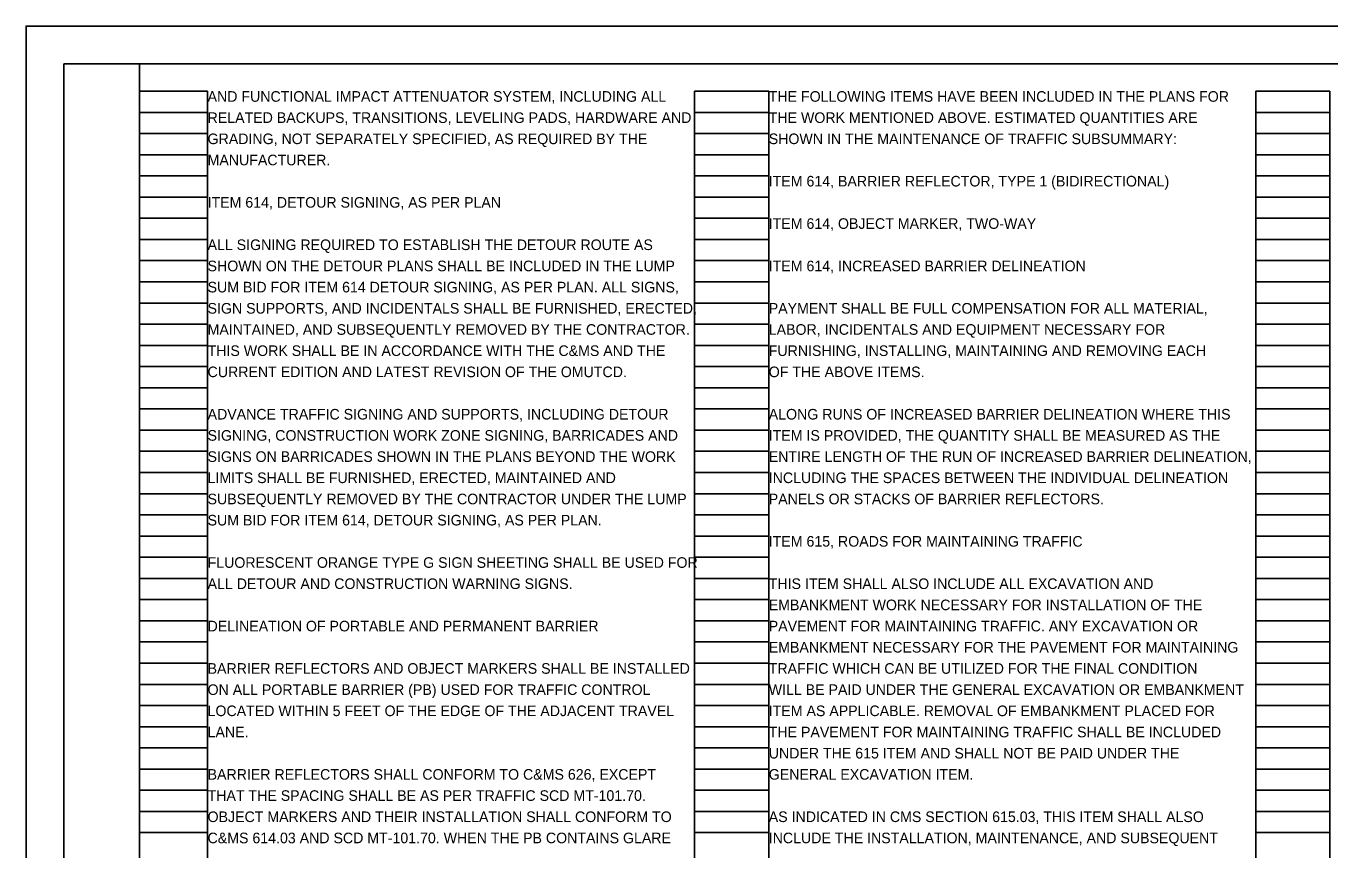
# Model space of a CAD drawing. Extents: x -50 to 112, y -27 to 22.
# Drawn here: x 78 to 95.24, y 11.11 to 22 of the extents above; entities that cross this region are included whole.
import ezdxf

# ---------------------------------------------------------------- set-up
doc = ezdxf.new("R2010")
doc.units = 0
for name, color, linetype in [('SC_Scratch1', 7, 'Continuous'), ('SH_Border', 7, 'Continuous'), ('SH_Cut_Line', 7, 'Continuous'), ('SH_Text', 7, 'Continuous')]:
    doc.layers.add(name, color=color, linetype=linetype)

msp = doc.modelspace()

# ---------------------------------------------------------------- linework, layer by layer
at = {"layer": 'SC_Scratch1'}
for p, q in [((79.5, 0.98), (79.5, 21.14)), ((79.5, 21.14), (80.4, 21.14)), ((80.4, 0.98), (80.4, 21.14)), ((86.84, 0.98), (86.84, 21.14)), ((86.84, 21.14), (87.82, 21.14)), ((87.82, 0.98), (87.82, 21.14)), ((94.26, 0.98), (94.26, 21.14)), ((94.26, 21.14), (95.24, 21.14)), ((95.24, 0.98), (95.24, 21.14)), ((79.5, 20.86), (80.4, 20.86)), ((86.84, 20.86), (87.82, 20.86)), ((94.26, 20.86), (95.24, 20.86)), ((79.5, 20.58), (80.4, 20.58)), ((86.84, 20.58), (87.82, 20.58)), ((94.26, 20.58), (95.24, 20.58)), ((79.5, 20.3), (80.4, 20.3)), ((86.84, 20.3), (87.82, 20.3)), ((94.26, 20.3), (95.24, 20.3)), ((79.5, 20.02), (80.4, 20.02)), ((86.84, 20.02), (87.82, 20.02)), ((94.26, 20.02), (95.24, 20.02)), ((79.5, 19.74), (80.4, 19.74)), ((86.84, 19.74), (87.82, 19.74)), ((94.26, 19.74), (95.24, 19.74)), ((79.5, 19.46), (80.4, 19.46)), ((86.84, 19.46), (87.82, 19.46)), ((94.26, 19.46), (95.24, 19.46)), ((79.5, 19.18), (80.4, 19.18)), ((86.84, 19.18), (87.82, 19.18)), ((94.26, 19.18), (95.24, 19.18)), ((79.5, 18.9), (80.4, 18.9)), ((86.84, 18.9), (87.82, 18.9)), ((94.26, 18.9), (95.24, 18.9)), ((79.5, 18.62), (80.4, 18.62)), ((86.84, 18.62), (87.82, 18.62)), ((94.26, 18.62), (95.24, 18.62)), ((79.5, 18.34), (80.4, 18.34)), ((86.84, 18.34), (87.82, 18.34)), ((94.26, 18.34), (95.24, 18.34)), ((79.5, 18.06), (80.4, 18.06)), ((86.84, 18.06), (87.82, 18.06)), ((94.26, 18.06), (95.24, 18.06)), ((79.5, 17.78), (80.4, 17.78)), ((86.84, 17.78), (87.82, 17.78)), ((94.26, 17.78), (95.24, 17.78)), ((79.5, 17.5), (80.4, 17.5)), ((86.84, 17.5), (87.82, 17.5)), ((94.26, 17.5), (95.24, 17.5)), ((79.5, 17.22), (80.4, 17.22)), ((86.84, 17.22), (87.82, 17.22)), ((94.26, 17.22), (95.24, 17.22)), ((79.5, 16.94), (80.4, 16.94)), ((86.84, 16.94), (87.82, 16.94)), ((94.26, 16.94), (95.24, 16.94)), ((79.5, 16.66), (80.4, 16.66)), ((86.84, 16.66), (87.82, 16.66)), ((94.26, 16.66), (95.24, 16.66)), ((79.5, 16.38), (80.4, 16.38)), ((86.84, 16.38), (87.82, 16.38)), ((94.26, 16.38), (95.24, 16.38)), ((79.5, 16.1), (80.4, 16.1)), ((86.84, 16.1), (87.82, 16.1)), ((94.26, 16.1), (95.24, 16.1)), ((79.5, 15.82), (80.4, 15.82)), ((86.84, 15.82), (87.82, 15.82)), ((94.26, 15.82), (95.24, 15.82)), ((79.5, 15.54), (80.4, 15.54)), ((86.84, 15.54), (87.82, 15.54)), ((94.26, 15.54), (95.24, 15.54)), ((79.5, 15.26), (80.4, 15.26)), ((86.84, 15.26), (87.82, 15.26)), ((94.26, 15.26), (95.24, 15.26)), ((79.5, 14.98), (80.4, 14.98)), ((86.84, 14.98), (87.82, 14.98)), ((94.26, 14.98), (95.24, 14.98)), ((79.5, 14.7), (80.4, 14.7)), ((86.84, 14.7), (87.82, 14.7)), ((94.26, 14.7), (95.24, 14.7)), ((79.5, 14.42), (80.4, 14.42)), ((86.84, 14.42), (87.82, 14.42)), ((94.26, 14.42), (95.24, 14.42)), ((79.5, 14.14), (80.4, 14.14)), ((86.84, 14.14), (87.82, 14.14)), ((94.26, 14.14), (95.24, 14.14)), ((79.5, 13.86), (80.4, 13.86)), ((86.84, 13.86), (87.82, 13.86)), ((94.26, 13.86), (95.24, 13.86)), ((79.5, 13.58), (80.4, 13.58)), ((86.84, 13.58), (87.82, 13.58)), ((94.26, 13.58), (95.24, 13.58)), ((79.5, 13.3), (80.4, 13.3)), ((86.84, 13.3), (87.82, 13.3)), ((94.26, 13.3), (95.24, 13.3)), ((79.5, 13.02), (80.4, 13.02)), ((86.84, 13.02), (87.82, 13.02)), ((94.26, 13.02), (95.24, 13.02)), ((79.5, 12.74), (80.4, 12.74)), ((86.84, 12.74), (87.82, 12.74)), ((94.26, 12.74), (95.24, 12.74)), ((79.5, 12.46), (80.4, 12.46)), ((86.84, 12.46), (87.82, 12.46)), ((94.26, 12.46), (95.24, 12.46)), ((79.5, 12.18), (80.4, 12.18)), ((86.84, 12.18), (87.82, 12.18)), ((94.26, 12.18), (95.24, 12.18)), ((79.5, 11.9), (80.4, 11.9)), ((86.84, 11.9), (87.82, 11.9)), ((94.26, 11.9), (95.24, 11.9)), ((79.5, 11.62), (80.4, 11.62)), ((86.84, 11.62), (87.82, 11.62)), ((94.26, 11.62), (95.24, 11.62)), ((79.5, 11.34), (80.4, 11.34)), ((86.84, 11.34), (87.82, 11.34)), ((94.26, 11.34), (95.24, 11.34))]:
    msp.add_line(p, q, dxfattribs=at)
at = {"layer": 'SH_Border'}
for points in [[(78.5, 21.5), (79.5, 21.5), (79.5, 0.5), (78.5, 0.5)], [(79.5, 21.5), (111.5, 21.5), (111.5, 0.5), (79.5, 0.5)]]:
    msp.add_lwpolyline(points, close=True, dxfattribs=at)
at = {"layer": 'SH_Cut_Line'}
msp.add_lwpolyline([(78, 0), (112, 0), (112, 22), (78, 22)], close=True, dxfattribs=at)

# ---------------------------------------------------------------- texts
at = {"layer": 'SH_Text'}
for s, p in [('AND FUNCTIONAL IMPACT ATTENUATOR SYSTEM, INCLUDING ALL ', (80.4, 21)), ('THE FOLLOWING ITEMS HAVE BEEN INCLUDED IN THE PLANS FOR', (87.82, 21)), ('RELATED BACKUPS, TRANSITIONS, LEVELING PADS, HARDWARE AND ', (80.4, 20.72)), ('THE WORK MENTIONED ABOVE. ESTIMATED QUANTITIES ARE ', (87.82, 20.72)), ('GRADING, NOT SEPARATELY SPECIFIED, AS REQUIRED BY THE ', (80.4, 20.44)), ('SHOWN IN THE MAINTENANCE OF TRAFFIC SUBSUMMARY:', (87.82, 20.44)), ('MANUFACTURER.', (80.4, 20.16)), ('ITEM 614, BARRIER REFLECTOR, TYPE 1 (BIDIRECTIONAL)', (87.82, 19.88)), ('ITEM 614, DETOUR SIGNING, AS PER PLAN', (80.4, 19.6)), ('ITEM 614, OBJECT MARKER, TWO-WAY', (87.82, 19.32)), ('ALL SIGNING REQUIRED TO ESTABLISH THE DETOUR ROUTE AS ', (80.4, 19.04)), ('SHOWN ON THE DETOUR PLANS SHALL BE INCLUDED IN THE LUMP ', (80.4, 18.76)), ('ITEM 614, INCREASED BARRIER DELINEATION', (87.82, 18.76)), ('SUM BID FOR ITEM 614 DETOUR SIGNING, AS PER PLAN. ALL SIGNS, ', (80.4, 18.48)), ('SIGN SUPPORTS, AND INCIDENTALS SHALL BE FURNISHED, ERECTED, ', (80.4, 18.2)), ('PAYMENT SHALL BE FULL COMPENSATION FOR ALL MATERIAL,', (87.82, 18.2)), ('MAINTAINED, AND SUBSEQUENTLY REMOVED BY THE CONTRACTOR. ', (80.4, 17.92)), ('LABOR, INCIDENTALS AND EQUIPMENT NECESSARY FOR ', (87.82, 17.92)), ('THIS WORK SHALL BE IN ACCORDANCE WITH THE C&MS AND THE ', (80.4, 17.64)), ('FURNISHING, INSTALLING, MAINTAINING AND REMOVING EACH', (87.82, 17.64)), ('CURRENT EDITION AND LATEST REVISION OF THE OMUTCD. ', (80.4, 17.36)), ('OF THE ABOVE ITEMS.', (87.82, 17.36)), ('ADVANCE TRAFFIC SIGNING AND SUPPORTS, INCLUDING DETOUR ', (80.4, 16.8)), ('ALONG RUNS OF INCREASED BARRIER DELINEATION WHERE THIS ', (87.82, 16.8)), ('SIGNING, CONSTRUCTION WORK ZONE SIGNING, BARRICADES AND ', (80.4, 16.52)), ('ITEM IS PROVIDED, THE QUANTITY SHALL BE MEASURED AS THE ', (87.82, 16.52)), ('SIGNS ON BARRICADES SHOWN IN THE PLANS BEYOND THE WORK ', (80.4, 16.24)), ('ENTIRE LENGTH OF THE RUN OF INCREASED BARRIER DELINEATION, ', (87.82, 16.24)), ('LIMITS SHALL BE FURNISHED, ERECTED, MAINTAINED AND ', (80.4, 15.96)), ('INCLUDING THE SPACES BETWEEN THE INDIVIDUAL DELINEATION ', (87.82, 15.96)), ('SUBSEQUENTLY REMOVED BY THE CONTRACTOR UNDER THE LUMP ', (80.4, 15.68)), ('PANELS OR STACKS OF BARRIER REFLECTORS.', (87.82, 15.68)), ('SUM BID FOR ITEM 614, DETOUR SIGNING, AS PER PLAN.', (80.4, 15.4)), ('ITEM 615, ROADS FOR MAINTAINING TRAFFIC', (87.82, 15.12)), ('FLUORESCENT ORANGE TYPE G SIGN SHEETING SHALL BE USED FOR ', (80.4, 14.84)), ('ALL DETOUR AND CONSTRUCTION WARNING SIGNS.', (80.4, 14.56)), ('THIS ITEM SHALL ALSO INCLUDE ALL EXCAVATION AND', (87.82, 14.56)), ('EMBANKMENT WORK NECESSARY FOR INSTALLATION OF THE', (87.82, 14.28)), ('DELINEATION OF PORTABLE AND PERMANENT BARRIER', (80.4, 14)), ('PAVEMENT FOR MAINTAINING TRAFFIC. ANY EXCAVATION OR ', (87.82, 14)), ('EMBANKMENT NECESSARY FOR THE PAVEMENT FOR MAINTAINING ', (87.82, 13.72)), ('BARRIER REFLECTORS AND OBJECT MARKERS SHALL BE INSTALLED ', (80.4, 13.44)), ('TRAFFIC WHICH CAN BE UTILIZED FOR THE FINAL CONDITION ', (87.82, 13.44)), ('ON ALL PORTABLE BARRIER (PB) USED FOR TRAFFIC CONTROL ', (80.4, 13.16)), ('WILL BE PAID UNDER THE GENERAL EXCAVATION OR EMBANKMENT ', (87.82, 13.16)), ('LOCATED WITHIN 5 FEET OF THE EDGE OF THE ADJACENT TRAVEL ', (80.4, 12.88)), ('ITEM AS APPLICABLE. REMOVAL OF EMBANKMENT PLACED FOR ', (87.82, 12.88)), ('LANE.', (80.4, 12.6)), ('THE PAVEMENT FOR MAINTAINING TRAFFIC SHALL BE INCLUDED ', (87.82, 12.6)), ('UNDER THE 615 ITEM AND SHALL NOT BE PAID UNDER THE ', (87.82, 12.32)), ('BARRIER REFLECTORS SHALL CONFORM TO C&MS 626, EXCEPT ', (80.4, 12.04)), ('GENERAL EXCAVATION ITEM.', (87.82, 12.04)), ('THAT THE SPACING SHALL BE AS PER TRAFFIC SCD MT-101.70. ', (80.4, 11.76)), ('OBJECT MARKERS AND THEIR INSTALLATION SHALL CONFORM TO ', (80.4, 11.48)), ('AS INDICATED IN CMS SECTION 615.03, THIS ITEM SHALL ALSO ', (87.82, 11.48)), ('C&MS 614.03 AND SCD MT-101.70. WHEN THE PB CONTAINS GLARE ', (80.4, 11.2)), ('INCLUDE THE INSTALLATION, MAINTENANCE, AND SUBSEQUENT ', (87.82, 11.2))]:
    msp.add_text(s, height=0.14, dxfattribs=at).set_placement(p)

doc.saveas('drawing.dxf')
